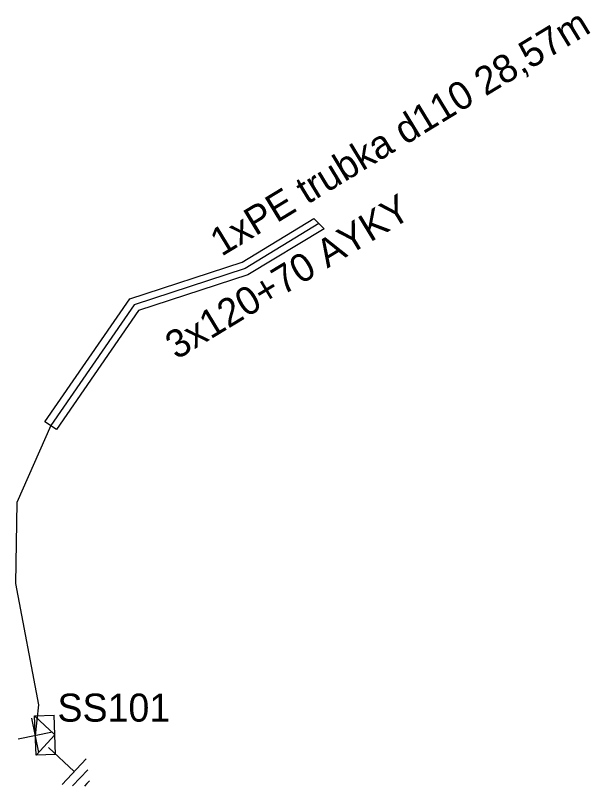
# Model space of a CAD drawing. Extents: x -737417 to -734469, y -1145580 to -1142703.
# Drawn here: x -736760.93 to -736740.46, y -1145288.95 to -1145261.12 of the extents above; entities that cross this region are included whole.
import ezdxf

# ---------------------------------------------------------------- set-up
doc = ezdxf.new("R2010")
doc.units = 0
for name, color, linetype in [('Vrstva 1', 7, 'Continuous'), ('Vrstva 14', 7, 'Continuous'), ('Vrstva 15', 7, 'Continuous'), ('Vrstva 20', 7, 'Continuous'), ('Vrstva 21', 7, 'Continuous'), ('Vrstva 31', 7, 'Continuous'), ('Vrstva 33', 7, 'Continuous'), ('Vrstva 34', 7, 'Continuous'), ('Vrstva 52', 7, 'Continuous'), ('Vrstva 54', 7, 'Continuous'), ('Vrstva 9', 7, 'Continuous')]:
    doc.layers.add(name, color=color, linetype=linetype)

# ---------------------------------------------------------------- blocks, each defined once
blk = doc.blocks.new('NN800')
at = {"layer": 'Vrstva 1'}
for points in [[(-0.442, 0.442), (0.442, -0.442)], [(-0.442, -0.442), (0.442, 0.442)]]:
    blk.add_lwpolyline(points, dxfattribs=at)
blk = doc.blocks.new('NN630')
at = {"layer": 'Vrstva 9'}
for points in [[(-0.003, -0.7), (-0.703, 0)], [(-0.703, -0.7), (-0.703, 0), (0.697, 0), (0.697, -0.7)], [(-0.003, -0.7), (0.697, 0)], [(-0.703, -0.7), (0.697, -0.7)]]:
    blk.add_lwpolyline(points, dxfattribs=at)
blk = doc.blocks.new('NN810')
at = {"layer": 'Vrstva 14'}
for points in [[(0.004, -0.64), (0.004, -1.89)], [(0.629, -1.89), (-0.621, -1.89)], [(0.388, -2.2), (-0.399, -2.2)], [(0.004, -2.515), (-0.124, -2.515)], [(0.137, -2.515), (0.004, -2.515)]]:
    blk.add_lwpolyline(points, dxfattribs=at)

msp = doc.modelspace()

# ---------------------------------------------------------------- linework, layer by layer
at = {"layer": 'Vrstva 20'}
msp.add_lwpolyline([(-736750.312, -1145268.359), (-736749.941, -1145268.72), (-736752.655, -1145270.369), (-736756.552, -1145271.641), (-736759.474, -1145275.882), (-736759.886, -1145275.598), (-736756.868, -1145271.219), (-736752.865, -1145269.911)], close=True, dxfattribs=at)
at = {"layer": 'Vrstva 52'}
msp.add_lwpolyline([(-736750.127, -1145268.54), (-736752.76, -1145270.14), (-736756.71, -1145271.43), (-736759.68, -1145275.74), (-736760.89, -1145278.48), (-736760.93, -1145281.37), (-736760.11, -1145285.69), (-736760.23, -1145286.78)], dxfattribs=at)

# ---------------------------------------------------------------- block references
at = {"layer": 'Vrstva 15', "rotation": 46.801235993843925}
msp.add_blockref('NN810', (-736760.23, -1145286.78), dxfattribs=at)
at = {"layer": 'Vrstva 31', "rotation": 92.09515559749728}
msp.add_blockref('NN630', (-736760.23, -1145286.78), dxfattribs=at)
at = {"layer": 'Vrstva 34', "rotation": 56.65928053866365}
msp.add_blockref('NN800', (-736760.23, -1145286.78), dxfattribs=at)

# ---------------------------------------------------------------- texts
at = {"layer": 'Vrstva 21'}
msp.add_text('1xPE trubka d110 28,57m', height=1, rotation=31.289, dxfattribs=at).set_placement((-736753.6, -1145269.727))
at = {"layer": 'Vrstva 33'}
msp.add_text('SS101', height=1, dxfattribs=at).set_placement((-736759.44, -1145286.29))
at = {"layer": 'Vrstva 54'}
msp.add_text('3x120+70 AYKY', height=1, rotation=31.285, dxfattribs=at).set_placement((-736755.2, -1145273.407))

doc.saveas('drawing.dxf')
